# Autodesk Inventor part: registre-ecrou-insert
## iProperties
Author: chr
Created: 2001-06
Part Number: registre-ecrou-insert
Material: Par défaut
Document SubType Name: Modélisation
Designer: chr
Control State: 0
Master: False
Checked Out: False
PropertySet Name: Design Tracking Control
Shininess: 20.0
PropertySet Name: _Private Model Information
Length Units: 11272
Angle Units: 11286
Time Units: 11279
Mass Units: 11290
Length Display Precision: 3
Angle Display Precision: 2
Compacted: False
Density: 0.0
Volumn: 0.0
Area: 0.0
PropertySet Name: Model Information
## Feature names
1. Extrusion1
2. Extrusion2
